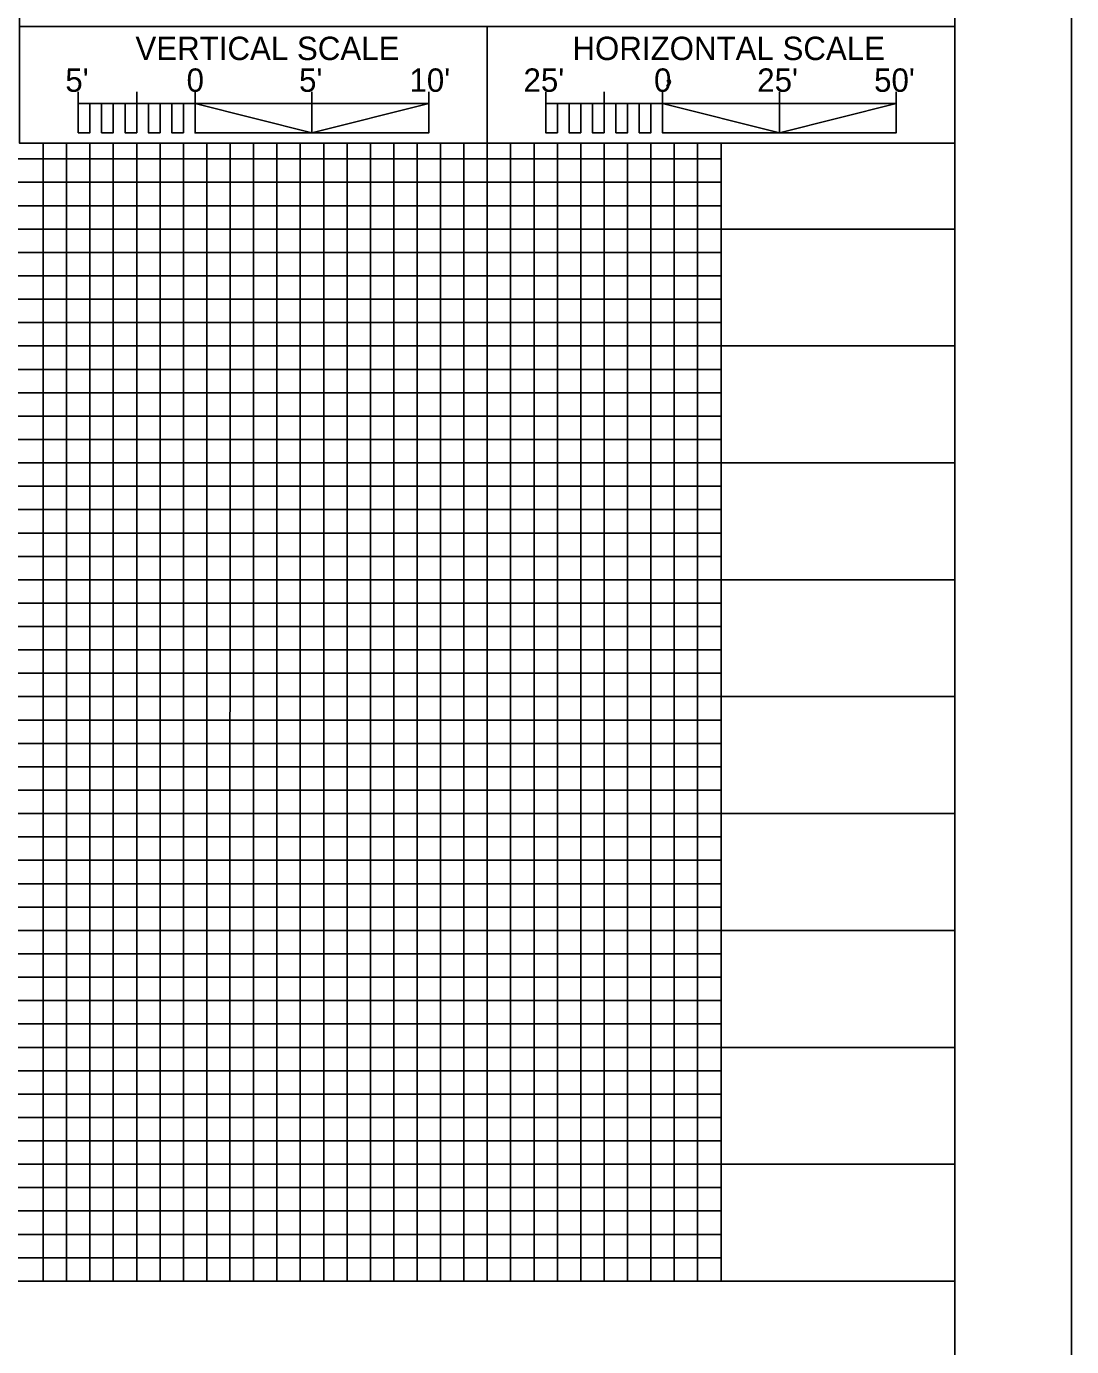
# Model space of a CAD drawing. Extents: x 2474053 to 2475957, y 620456 to 621556.
# Drawn here: x 2475529.3 to 2475752.9, y 621017.1 to 621299.5 of the extents above; entities that cross this region are included whole.
import ezdxf

# ---------------------------------------------------------------- set-up
doc = ezdxf.new("R2010")
doc.units = 0
for name, color, linetype in [('Old_Level_18', 7, 'Continuous'), ('Old_Level_38', 7, 'Continuous'), ('Old_Level_40', 7, 'Continuous'), ('Old_Level_62', 7, 'Continuous'), ('Old_Level_63', 7, 'Continuous'), ('Scratch_Level_3', 7, 'Continuous'), ('Sheet Profile CELL', 7, 'Continuous'), ('Sheet Profile Grid Major CELL', 7, 'Continuous'), ('Sheet Profile Grid Middle CELL', 7, 'Continuous'), ('Sheet Profile Grid Minor CELL', 7, 'Continuous'), ('Typical Text Grade Point CELL', 7, 'Continuous')]:
    doc.layers.add(name, color=color, linetype=linetype)

msp = doc.modelspace()

# ---------------------------------------------------------------- linework, layer by layer
at = {"layer": 'Old_Level_18'}
msp.add_lwpolyline([(2475727.88, 621531.13), (2474227.88, 621531.13), (2474227.88, 620481.13), (2475727.88, 620481.13)], close=True, dxfattribs=at)
at = {"layer": 'Old_Level_38'}
for p, q in [((2475540.38, 621285.49), (2475540.38, 621276.74)), ((2475615.38, 621282.99), (2475540.38, 621282.99)), ((2475540.38, 621282.99), (2475540.38, 621276.74)), ((2475552.88, 621285.49), (2475552.88, 621276.74)), ((2475565.38, 621285.49), (2475565.38, 621276.69)), ((2475590.38, 621285.49), (2475590.38, 621276.74)), ((2475615.38, 621285.49), (2475615.38, 621276.74)), ((2475615.38, 621276.74), (2475615.38, 621282.99)), ((2475640.38, 621285.49), (2475640.38, 621276.74)), ((2475715.38, 621282.99), (2475640.38, 621282.99)), ((2475652.88, 621285.49), (2475652.88, 621276.74)), ((2475665.38, 621285.49), (2475665.38, 621276.69)), ((2475690.38, 621285.49), (2475690.38, 621276.74)), ((2475715.38, 621285.49), (2475715.38, 621276.74)), ((2475715.38, 621276.74), (2475715.38, 621282.99))]:
    msp.add_line(p, q, dxfattribs=at)
for points in [[(2475542.88, 621282.99), (2475540.38, 621282.99), (2475540.38, 621276.74), (2475542.88, 621276.74)], [(2475545.38, 621282.99), (2475547.88, 621282.99), (2475547.88, 621276.74), (2475545.38, 621276.74)], [(2475550.38, 621282.99), (2475552.88, 621282.99), (2475552.88, 621276.74), (2475550.38, 621276.74)], [(2475555.38, 621282.99), (2475557.88, 621282.99), (2475557.88, 621276.74), (2475555.38, 621276.74)], [(2475560.38, 621282.99), (2475562.88, 621282.99), (2475562.88, 621276.74), (2475560.38, 621276.74)], [(2475565.38, 621282.99), (2475590.38, 621276.69), (2475565.38, 621276.69)], [(2475590.38, 621276.69), (2475615.38, 621282.99), (2475615.38, 621276.74)], [(2475642.88, 621282.99), (2475640.38, 621282.99), (2475640.38, 621276.74), (2475642.88, 621276.74)], [(2475645.38, 621282.99), (2475647.88, 621282.99), (2475647.88, 621276.74), (2475645.38, 621276.74)], [(2475650.38, 621282.99), (2475652.88, 621282.99), (2475652.88, 621276.74), (2475650.38, 621276.74)], [(2475655.38, 621282.99), (2475657.88, 621282.99), (2475657.88, 621276.74), (2475655.38, 621276.74)], [(2475660.38, 621282.99), (2475662.88, 621282.99), (2475662.88, 621276.74), (2475660.38, 621276.74)], [(2475665.38, 621282.99), (2475690.38, 621276.69), (2475665.38, 621276.69)], [(2475690.38, 621276.69), (2475715.38, 621282.99), (2475715.38, 621276.74)]]:
    msp.add_lwpolyline(points, close=True, dxfattribs=at)
at = {"layer": 'Old_Level_40'}
msp.add_line((2475627.85, 621299.48), (2475627.85, 621274.49), dxfattribs=at)
msp.add_lwpolyline([(2475527.83, 621274.49), (2475727.88, 621274.49), (2475727.88, 621299.48), (2475527.83, 621299.48)], close=True, dxfattribs=at)
at = {"layer": 'Old_Level_62'}
msp.add_lwpolyline([(2474077.88, 620481.13), (2475727.88, 620481.13), (2475727.88, 621531.13), (2474077.88, 621531.13)], close=True, dxfattribs=at)
at = {"layer": 'Old_Level_63'}
msp.add_lwpolyline([(2474052.88, 620456.13), (2475752.88, 620456.13), (2475752.88, 621556.13), (2474052.88, 621556.13)], close=True, dxfattribs=at)
at = {"layer": 'Scratch_Level_3'}
msp.add_lwpolyline([(2474227.88, 621531.13), (2474227.88, 620481.13), (2475727.88, 620481.13), (2475727.88, 621274.49), (2475527.83, 621274.49), (2475527.83, 621531.13)], close=True, dxfattribs=at)
at = {"layer": 'Sheet Profile CELL'}
msp.add_line((2474227.88, 621031.13), (2475727.88, 621031.13), dxfattribs=at)
at = {"layer": 'Sheet Profile Grid Major CELL'}
for p, q in [((2475577.88, 621274.49), (2475577.88, 621031.13)), ((2475627.88, 621031.13), (2475627.88, 621274.49)), ((2475677.88, 621274.49), (2475677.88, 621031.13)), ((2475727.88, 621231.13), (2474227.88, 621231.13)), ((2474227.88, 621181.13), (2475727.88, 621181.13)), ((2475727.88, 621131.13), (2474227.88, 621131.13)), ((2474227.88, 621081.13), (2475727.88, 621081.13)), ((2474227.88, 621031.13), (2475727.88, 621031.13))]:
    msp.add_line(p, q, dxfattribs=at)
at = {"layer": 'Sheet Profile Grid Middle CELL'}
for p, q in [((2475552.88, 621274.49), (2475552.88, 621031.13)), ((2475552.88, 621031.13), (2475552.88, 621274.49)), ((2475602.88, 621274.49), (2475602.88, 621031.13)), ((2475602.88, 621031.13), (2475602.88, 621274.49)), ((2475652.88, 621031.13), (2475652.88, 621274.49)), ((2475727.88, 621256.13), (2474227.88, 621256.13)), ((2474227.88, 621206.13), (2475727.88, 621206.13)), ((2475727.88, 621156.13), (2474227.88, 621156.13)), ((2474227.88, 621106.13), (2475727.88, 621106.13)), ((2475727.88, 621056.13), (2474227.88, 621056.13))]:
    msp.add_line(p, q, dxfattribs=at)
at = {"layer": 'Sheet Profile Grid Minor CELL'}
for p, q in [((2475532.88, 621274.49), (2475532.88, 621031.13)), ((2475537.88, 621031.13), (2475537.88, 621274.49)), ((2475542.88, 621274.49), (2475542.88, 621031.13)), ((2475547.88, 621031.13), (2475547.88, 621274.49)), ((2475557.88, 621274.49), (2475557.88, 621031.13)), ((2475562.88, 621274.49), (2475562.88, 621031.13)), ((2475567.88, 621031.13), (2475567.88, 621274.49)), ((2475572.85, 621274.49), (2475572.78, 621031.18)), ((2475582.88, 621031.13), (2475582.88, 621274.49)), ((2475582.88, 621274.49), (2475582.88, 621031.13)), ((2475587.88, 621031.13), (2475587.88, 621274.49)), ((2475592.88, 621274.49), (2475592.88, 621031.13)), ((2475597.88, 621031.13), (2475597.88, 621274.49)), ((2475607.88, 621274.49), (2475607.88, 621031.13)), ((2475612.88, 621031.13), (2475612.88, 621274.49)), ((2475617.88, 621274.49), (2475617.88, 621031.13)), ((2475622.88, 621031.13), (2475622.88, 621274.49)), ((2475632.88, 621274.49), (2475632.88, 621031.13)), ((2475637.88, 621031.13), (2475637.88, 621274.49)), ((2475642.88, 621274.49), (2475642.88, 621031.13)), ((2475647.88, 621031.13), (2475647.88, 621274.49)), ((2475657.88, 621274.49), (2475657.88, 621031.13)), ((2475662.88, 621031.13), (2475662.88, 621274.49)), ((2475667.88, 621274.49), (2475667.88, 621031.13)), ((2475672.88, 621031.13), (2475672.88, 621274.49)), ((2475677.88, 621271.13), (2474277.88, 621271.13)), ((2474277.88, 621266.13), (2475677.88, 621266.13)), ((2475677.88, 621261.13), (2474277.88, 621261.13)), ((2474277.88, 621251.13), (2475677.88, 621251.13)), ((2475677.88, 621246.13), (2474277.88, 621246.13)), ((2474277.88, 621241.13), (2475677.88, 621241.13)), ((2475677.88, 621236.13), (2474277.88, 621236.13)), ((2474277.88, 621226.13), (2475677.88, 621226.13)), ((2475677.88, 621221.13), (2474277.88, 621221.13)), ((2474277.88, 621216.13), (2475677.88, 621216.13)), ((2475677.88, 621211.13), (2474277.88, 621211.13)), ((2474277.88, 621201.13), (2475677.88, 621201.13)), ((2475677.88, 621196.13), (2474277.88, 621196.13)), ((2474277.88, 621191.13), (2475677.88, 621191.13)), ((2475677.88, 621186.13), (2474277.88, 621186.13)), ((2474277.88, 621176.13), (2475677.88, 621176.13)), ((2475677.88, 621171.13), (2474277.88, 621171.13)), ((2474277.88, 621166.13), (2475677.88, 621166.13)), ((2475677.88, 621161.13), (2474277.88, 621161.13)), ((2474277.88, 621151.13), (2475677.88, 621151.13)), ((2475677.88, 621146.13), (2474277.88, 621146.13)), ((2475677.88, 621141.13), (2474277.88, 621141.13)), ((2475677.88, 621136.13), (2474277.88, 621136.13)), ((2474277.88, 621126.13), (2475677.88, 621126.13)), ((2475677.88, 621121.13), (2474277.88, 621121.13)), ((2474277.88, 621116.13), (2475677.88, 621116.13)), ((2475677.88, 621111.13), (2474277.88, 621111.13)), ((2474277.88, 621101.13), (2475677.88, 621101.13)), ((2475677.88, 621096.13), (2474277.88, 621096.13)), ((2474277.88, 621091.13), (2475677.88, 621091.13)), ((2475677.88, 621086.13), (2474277.88, 621086.13)), ((2474277.88, 621076.13), (2475677.88, 621076.13)), ((2475677.88, 621071.13), (2474277.88, 621071.13)), ((2474277.88, 621066.13), (2475677.88, 621066.13)), ((2475677.88, 621061.13), (2474277.88, 621061.13)), ((2474277.88, 621051.13), (2475677.88, 621051.13)), ((2475677.88, 621046.13), (2474277.88, 621046.13)), ((2474277.88, 621041.13), (2475677.88, 621041.13)), ((2475677.88, 621036.13), (2474277.88, 621036.13))]:
    msp.add_line(p, q, dxfattribs=at)
at = {"layer": 'Typical Text Grade Point CELL'}
msp.add_lwpolyline([(2475667.06, 621287.67), (2475667.03, 621287.81), (2475666.93, 621287.95), (2475666.81, 621288.04), (2475666.68, 621288.07), (2475666.58, 621288.05), (2475666.49, 621288), (2475666.43, 621287.92), (2475666.41, 621287.82), (2475666.46, 621287.7), (2475666.56, 621287.6), (2475666.63, 621287.49), (2475666.62, 621287.35), (2475666.49, 621287.03), (2475666.31, 621286.72), (2475666.48, 621286.62), (2475666.84, 621287.14), (2475667.01, 621287.45)], close=True, dxfattribs=at)

# ---------------------------------------------------------------- texts
at = {"layer": 'Old_Level_40'}
for s, p in [('VERTICAL SCALE', (2475552.61, 621292.28)), ('HORIZONTAL SCALE', (2475646.09, 621292.28)), ("5'", (2475537.61, 621285.49)), ('0', (2475563.55, 621285.49)), ("5'", (2475587.61, 621285.49)), ("10'", (2475611.23, 621285.49)), ("25'", (2475635.63, 621285.49)), ('0', (2475663.55, 621285.49)), ("25'", (2475685.63, 621285.49)), ("50'", (2475710.63, 621285.49))]:
    msp.add_text(s, height=5, dxfattribs=at).set_placement(p)

doc.saveas('drawing.dxf')
